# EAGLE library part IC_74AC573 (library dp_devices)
8 Transparent Latch with 3-state output Mfr no: SN74AC573NSR Digikey
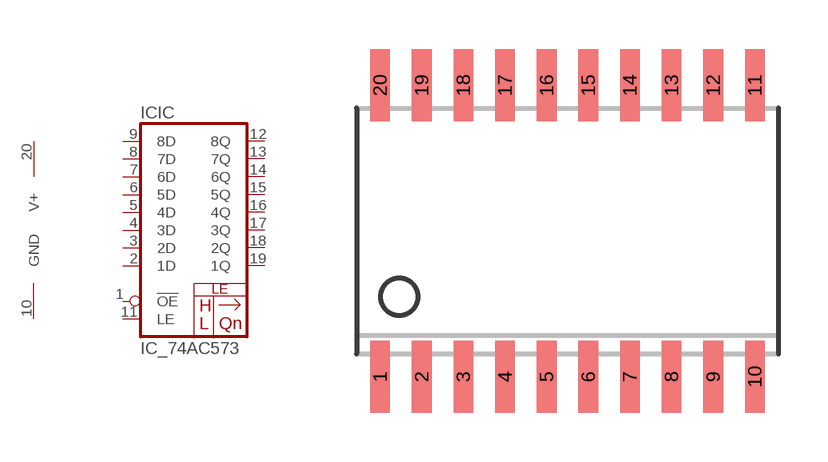
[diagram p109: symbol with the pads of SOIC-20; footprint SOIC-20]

Designator prefix IC; gates IC=74AC573 PWR=SUPPLY

## IC_74AC573  [SOIC-20]
1  IC:!OE  in
2  IC:1D
3  IC:2D
4  IC:3D
5  IC:4D
6  IC:5D
7  IC:6D
8  IC:7D
9  IC:8D
10  PWR:GND  sup
11  IC:LE  in
12  IC:8Q
13  IC:7Q
14  IC:6Q
15  IC:5Q
16  IC:4Q
17  IC:3Q
18  IC:2Q
19  IC:1Q
20  PWR:V+  sup

## Footprint SOIC-20 (pad centres in mm)
smd 0.6 x 2.2: 1 -5.715,-4.445; 2 -4.445,-4.445; 3 -3.175,-4.445; 4 -1.905,-4.445; 5 -0.635,-4.445; 6 0.635,-4.445; 7 1.905,-4.445; 8 3.175,-4.445; 9 4.445,-4.445; 10 5.715,-4.445; 11 5.715,4.445; 12 4.445,4.445; 13 3.175,4.445; 14 1.905,4.445; 15 0.635,4.445; 16 -0.635,4.445; 17 -1.905,4.445; 18 -3.175,4.445; 19 -4.445,4.445; 20 -5.715,4.445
